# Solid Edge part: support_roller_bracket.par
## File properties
Title: Support roller bracket
Author: Deepak Maini
Template: Normal.par
Last saved by: Robert a Rhodes jr
Revision: 15
Application: Solid Edge
Material: aluminum
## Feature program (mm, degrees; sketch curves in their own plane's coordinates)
sketch for "unnamed Protrusion 1" #1 plane through (0, 0, 0) normal (0, -1, 0) x-axis (1, 0, 0)
  circle centre (0, -138.9237) radius 3.81
sketch for "unnamed Protrusion 1" #2 plane through (0, 0, 0) normal (0, -1, 0) x-axis (1, 0, 0)
  line (143.637, -99.9249) -> (-143.637, -99.9249)
  line (-143.637, -99.9249) -> (-143.637, -115.1647)
  line (-143.637, -115.1647) -> (-61.0846, -156.7704)
  line (-61.0846, -156.7704) -> (-61.0846, -162.9363)
  line (-61.0846, -162.9363) -> (61.0846, -162.9363)
  line (61.0846, -156.7704) -> (61.0846, -162.9363)
  line (143.637, -115.1647) -> (61.0846, -156.7704)
  line (143.637, -99.9249) -> (143.637, -115.1647)
  dimension (linear) = 143.637
extrude "unnamed Protrusion 1" add finite 101.6 symmetric
fillet "unnamed Round 1"
fillet "unnamed Round 2"
sketch for "unnamed Protrusion 2" plane through (0, 0, 67.2512) normal (1, 0, 0) x-axis (0, 1, 0)
  arc centre (-23.4135, -61.792) radius 19.05 from (-23.4135, -42.742) to (-42.405, -60.3002) ccw
  line (-50.8, -167.1761) -> (-42.405, -60.3002)
  line (-50.8, -167.1761) -> (50.8, -167.1761)
  line (45.7777, -60.8928) -> (50.8, -167.1761)
  arc centre (26.749, -61.792) radius 19.05 from (26.749, -42.742) to (45.7777, -60.8928) cw
  line (19.05, -42.742) -> (26.749, -42.742)
  line (19.05, -64.967) -> (19.05, -42.742)
  arc centre (0, -64.967) radius 19.05 from (-19.05, -64.967) to (19.05, -64.967) ccw
  line (-19.05, -42.742) -> (-19.05, -64.967)
  line (-23.4135, -42.742) -> (-19.05, -42.742)
extrude "unnamed Protrusion 2" add to key point symmetric
sketch for "unnamed Cutout 1" plane through (0, 0, 0) normal (0, -1, 0) x-axis (1, 0, 0)
  line (-128.3193, 24.5092) -> (125.6319, 24.5092)
  line (125.6319, 24.5092) -> (125.6319, -99.9249)
  line (125.6319, -99.9249) -> (-128.3193, -99.9249)
  line (-128.3193, -99.9249) -> (-128.3193, 24.5092)
extrude "unnamed Cutout 1" cut finite 203.2 symmetric
chamfer "unnamed Chamfer 1"
rib "unnamed Rib 1"
mirror "unnamed Mirror 1" of "unnamed Rib 1" about plane through (0, 0, 0) normal (1, 0, 0)
rib "unnamed Rib 2"
sketch for "unnamed Hole 1" plane through (0.1259, 0, -162.9363) normal (0, 0, -1) x-axis (-1, 0, 0)
  hole centre (0.1259, 0) bore radius 25.4
hole "unnamed Hole 1" through
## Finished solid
Body 1: solid body, 55 faces, 142 edges, 86 vertices.
  Faces by surface: plane 38, cylinder 17
  Edges by curve: line 106, circle 34, intersection 2
Bounding box of the edges (mm): 379.121 x 101.600 x 187.446, from (-189.5605, -50.8, -162.9363) to (189.5605, 50.8, 24.5092).
Cylindrical faces by radius (mm): R3.81 x2, R6.35 x2, R19.05 x6, R25.4 x1, R31.75 x4, R55.372 x2
Planar faces by outward normal: +x 4, +y 5, +z 5, -x 4, -y 5, -z 1, oblique 14
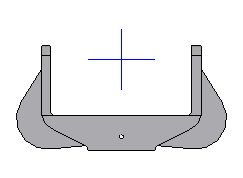
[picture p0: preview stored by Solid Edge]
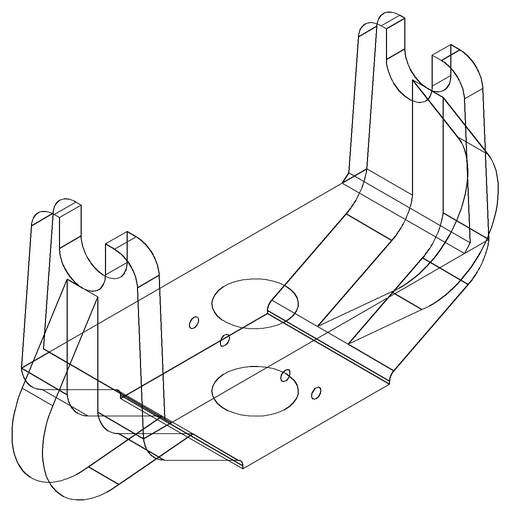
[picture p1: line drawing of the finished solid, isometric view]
